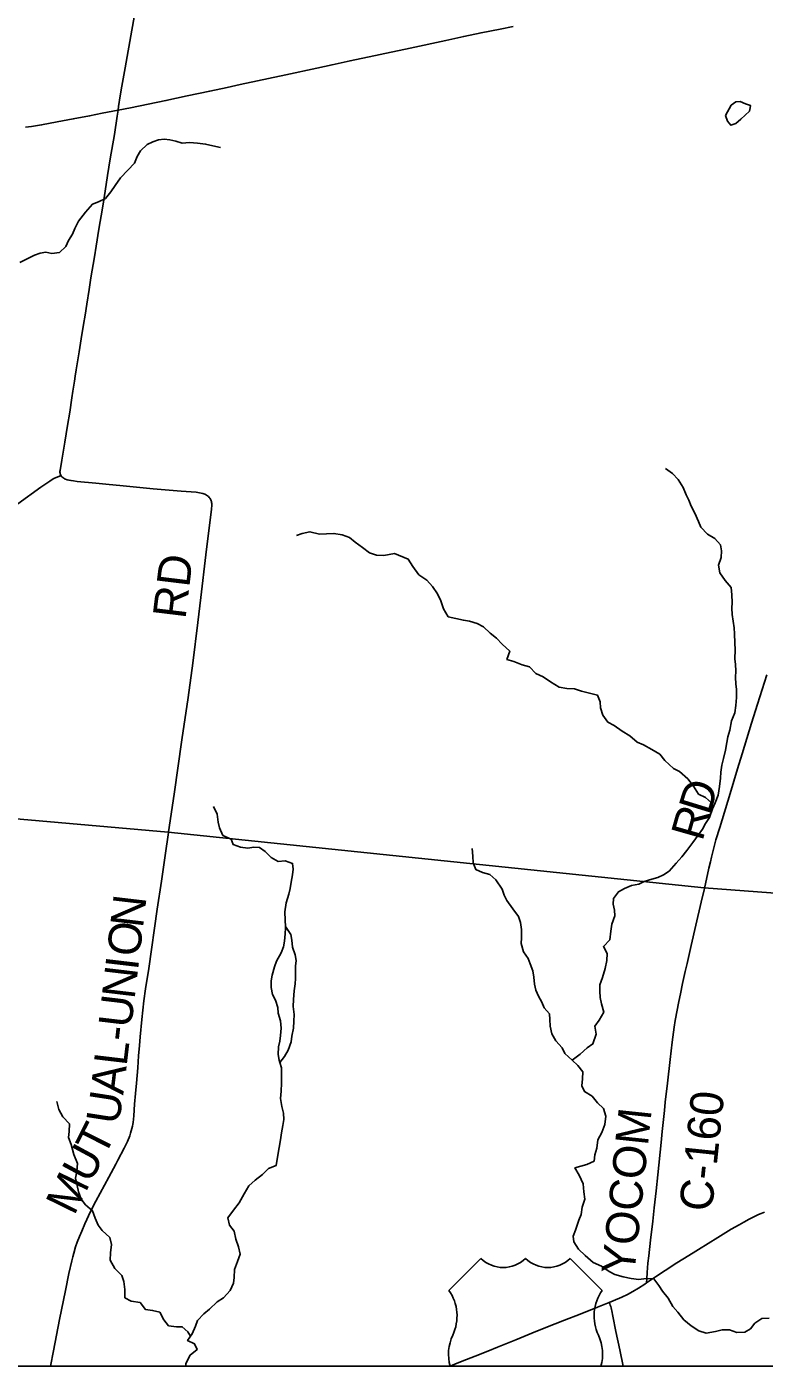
# Model space of a CAD drawing. Extents: x 0 to 1101, y 0 to 440.
# Drawn here: x 847.022 to 848.291, y 368.306 to 370.612 of the extents above; entities that cross this region are included whole.
import ezdxf

# ---------------------------------------------------------------- set-up
doc = ezdxf.new("R2010")
doc.units = 0
for name, color, linetype in [('GM_X_County_Road', 7, 'Continuous'), ('GM_X_County_Road_Text', 7, 'Continuous'), ('GM_X_Major_River_Text', 7, 'Continuous'), ('GM_X_Minor_Lake', 7, 'Continuous'), ('GM_X_Minor_River', 7, 'Continuous'), ('GM_X_Township', 7, 'Continuous'), ('GM_X_Township_Road', 7, 'Continuous'), ('GM_X_US_Location', 7, 'Continuous'), ('GM_X_US_Route', 7, 'Continuous'), ('SH_Cut_Line', 7, 'Continuous')]:
    doc.layers.add(name, color=color, linetype=linetype)

msp = doc.modelspace()

# ---------------------------------------------------------------- linework, layer by layer
at = {"layer": 'GM_X_County_Road'}
for points in [[(847.1792, 370.4686), (847.18, 370.4749), (847.183, 370.4935), (847.1858, 370.51), (847.1913, 370.5418), (847.2028, 370.6067), (847.2095, 370.6452)], [(847.1792, 370.4686), (847.2008, 370.473), (847.2616, 370.4855), (847.298, 370.4935), (847.3369, 370.5018), (847.3667, 370.5081), (847.3892, 370.5129), (847.4681, 370.5299), (847.521, 370.5412), (847.5476, 370.5472), (847.5786, 370.554), (847.6819, 370.5759), (847.7432, 370.5891), (847.7742, 370.5959), (847.804, 370.6021), (847.8369, 370.6086), (847.8595, 370.6129)], [(847.0197, 370.4396), (847.0251, 370.44), (847.0299, 370.4407), (847.0476, 370.4436), (847.0745, 370.4486), (847.102, 370.4537), (847.1301, 370.4591), (847.152, 370.4635), (847.1792, 370.4686)], [(847.0807, 369.84), (847.08, 369.8414), (847.0796, 369.8426), (847.0793, 369.844), (847.0791, 369.8454), (847.0791, 369.8467), (847.0793, 369.8484), (847.0821, 369.8662), (847.0844, 369.8801), (847.0874, 369.8974), (847.0923, 369.9261), (847.0961, 369.9488), (847.0997, 369.9734), (847.1014, 369.9851), (847.1039, 370.0023), (847.1052, 370.0108), (847.107, 370.0219), (847.1121, 370.0525), (847.1158, 370.0752), (847.1197, 370.0997), (847.1223, 370.1157), (847.1253, 370.1347), (847.1293, 370.1598), (847.1325, 370.1801), (847.1383, 370.2163), (847.1413, 370.2346), (847.1461, 370.2641), (847.1522, 370.3002), (847.155, 370.318), (847.1609, 370.3561), (847.1657, 370.3849), (847.1728, 370.4272), (847.1778, 370.4587), (847.1792, 370.4686)], [(847.266, 369.226), (847.2754, 369.2908), (847.2889, 369.3843), (847.2996, 369.4575), (847.3079, 369.5165), (847.3166, 369.5868), (847.3218, 369.6294), (847.3302, 369.7029), (847.3353, 369.7448), (847.3397, 369.7812), (847.3403, 369.7894), (847.3403, 369.7913), (847.3401, 369.7932), (847.3398, 369.7948), (847.3393, 369.7964), (847.3388, 369.7976), (847.3382, 369.7988), (847.3371, 369.8005), (847.3359, 369.802), (847.3347, 369.8033), (847.3331, 369.8048), (847.3315, 369.8059), (847.3299, 369.8069), (847.3285, 369.8076), (847.327, 369.8083), (847.3248, 369.809), (847.3221, 369.8096), (847.3134, 369.8108), (847.2879, 369.8128), (847.2396, 369.817), (847.1877, 369.822), (847.158, 369.8248), (847.1407, 369.8264), (847.1086, 369.8296), (847.1026, 369.8304), (847.0981, 369.831), (847.0947, 369.8317), (847.0915, 369.8325), (847.0888, 369.8334), (847.087, 369.8342), (847.0855, 369.8351), (847.084, 369.8361), (847.083, 369.837), (847.082, 369.8381), (847.081, 369.8393), (847.0807, 369.84)], [(848.1884, 369.1288), (848.1963, 369.1634), (848.1987, 369.1743), (848.2007, 369.1827), (848.2039, 369.196), (848.2083, 369.2121), (848.2147, 369.2336), (848.2326, 369.2924), (848.2455, 369.3346), (848.2535, 369.3607), (848.2694, 369.413), (848.2799, 369.4462), (848.2959, 369.4965)], [(847.0629, 368.3059), (847.068, 368.3322), (847.0785, 368.3865), (847.0884, 368.4365), (847.0945, 368.4657), (847.0993, 368.4875), (847.101, 368.4943), (847.1027, 368.5007), (847.106, 368.5113), (847.1087, 368.5193), (847.1127, 368.5293), (847.1165, 368.5385), (847.1219, 368.551), (847.1319, 368.5724), (847.1409, 368.5901), (847.1631, 368.6317), (847.1752, 368.6541), (847.1787, 368.6607), (847.1895, 368.6811), (847.1951, 368.6929), (847.1991, 368.7027), (847.2005, 368.7071), (847.2018, 368.7111), (847.2029, 368.7151), (847.2037, 368.719), (847.2044, 368.7225), (847.2049, 368.7258), (847.2056, 368.7312), (847.206, 368.7369), (847.2076, 368.7574), (847.209, 368.7753), (847.2106, 368.7933), (847.2129, 368.8199), (847.2145, 368.8403), (847.2159, 368.8583), (847.2171, 368.8731), (847.2199, 368.9028), (847.2236, 368.9349), (847.2266, 368.9557), (847.2319, 368.9908), (847.2465, 369.0929), (847.2538, 369.1414), (847.2573, 369.1654), (847.2601, 369.1851), (847.2659, 369.225), (847.266, 369.226)], [(848.0889, 368.4495), (848.0893, 368.4563), (848.09, 368.4673), (848.0913, 368.4832), (848.0928, 368.4961), (848.0958, 368.5232), (848.0996, 368.5559), (848.1022, 368.5787), (848.1053, 368.6078), (848.108, 368.6356), (848.1139, 368.6912), (848.1158, 368.7103), (848.1196, 368.7461), (848.1211, 368.7604), (848.1247, 368.7931), (848.1295, 368.8338), (848.1331, 368.864), (848.1363, 368.8899), (848.1381, 368.9015), (848.1443, 368.9338), (848.1471, 368.9472), (848.1509, 368.9648), (848.1555, 368.9854), (848.1587, 368.9993), (848.1657, 369.0302), (848.1738, 369.0653), (848.183, 369.1052), (848.1878, 369.1264), (848.1884, 369.1288)]]:
    msp.add_lwpolyline(points, dxfattribs=at)
msp.add_lwpolyline([(844.6555, 368.3059), (849.3843, 368.3059), (849.458, 369.0211), (849.1756, 369.0468), (848.9835, 369.0702), (848.1881, 369.1294), (847.2656, 369.2256), (846.5466, 369.2884), (846.0672, 369.3302), (844.8955, 369.3794), (844.7671, 369.3901), (844.6729, 368.4734)], close=True, dxfattribs=at)
at = {"layer": 'GM_X_Major_River_Text'}
for p, q in [((847.8036, 368.4914), (847.7487, 368.4365)), ((848.0124, 368.4365), (847.9575, 368.4914)), ((847.7507, 368.3059), (848.0104, 368.3059))]:
    msp.add_line(p, q, dxfattribs=at)
for centre, radius, start, end in [((847.8421, 368.5307), 0.0549, 225.573, 314.427), ((847.919, 368.5307), 0.0549, 225.573, 314.427), ((847.6857, 368.3924), 0.0769, 334.5471, 35.0009), ((848.0754, 368.3924), 0.0769, 144.9991, 205.4529), ((847.8248, 368.3266), 0.0769, 154.8319, 195.6613), ((847.9363, 368.3266), 0.0769, 344.3387, 25.1681)]:
    msp.add_arc(centre, radius, start, end, dxfattribs=at)
at = {"layer": 'GM_X_Minor_Lake'}
for points in [[(848.2672, 370.4728), (848.2679, 370.4768), (848.2589, 370.4796), (848.2499, 370.4839), (848.2423, 370.4833), (848.2347, 370.4773), (848.2249, 370.4596)], [(848.2249, 370.4596), (848.2282, 370.4501), (848.2337, 370.4428), (848.2425, 370.4457), (848.2513, 370.4531), (848.2586, 370.4602), (848.2663, 370.4673), (848.2672, 370.4728)]]:
    msp.add_lwpolyline(points, dxfattribs=at)
at = {"layer": 'GM_X_Minor_River'}
for points in [[(847.0099, 370.2067), (847.0229, 370.213), (847.0355, 370.2189), (847.0451, 370.2226), (847.0546, 370.2243), (847.0652, 370.2223), (847.0781, 370.2236), (847.0893, 370.2341), (847.0936, 370.2447), (847.1006, 370.2552), (847.1045, 370.2651), (847.1108, 370.2779), (847.1232, 370.2933), (847.1351, 370.3068), (847.1454, 370.3108), (847.1573, 370.3168), (847.1666, 370.3284), (847.1739, 370.3389), (847.1832, 370.3525), (847.1959, 370.3656), (847.2075, 370.3776), (847.2122, 370.3893), (847.2177, 370.3991), (847.2292, 370.41), (847.2392, 370.4144), (847.2487, 370.4177), (847.2586, 370.4187)], [(847.2586, 370.4187), (847.2681, 370.4178), (847.2783, 370.4154), (847.2892, 370.4122), (847.3022, 370.4132), (847.3158, 370.4122), (847.3298, 370.4105), (847.3423, 370.4077), (847.3556, 370.4048)], [(847.9609, 368.8331), (847.9746, 368.8432), (847.9868, 368.854), (847.9964, 368.861), (848.0023, 368.8776), (847.9999, 368.8913), (848.0073, 368.9018), (848.0151, 368.9157), (848.0111, 368.9298), (848.009, 368.9409), (848.0085, 368.9515), (848.0086, 368.9629), (848.013, 368.9753), (848.0178, 368.9908), (848.0207, 369.0048), (848.0208, 369.0166), (848.0146, 369.0284), (848.0254, 369.0404), (848.0275, 369.0548), (848.0292, 369.0673), (848.0344, 369.0816), (848.0338, 369.0911), (848.0313, 369.1014), (848.0322, 369.1112), (848.0403, 369.1229), (848.051, 369.1284), (848.0632, 369.1335), (848.0754, 369.136), (848.0849, 369.1407), (848.0978, 369.1447), (848.1084, 369.1476), (848.118, 369.152), (848.1279, 369.1586), (848.1399, 369.1721), (848.1495, 369.1833), (848.1584, 369.1942), (848.1684, 369.2077), (848.1777, 369.2201), (848.1851, 369.2306), (848.1905, 369.2403), (848.1971, 369.2509), (848.2023, 369.2656), (848.207, 369.2761), (848.2121, 369.2893), (848.2146, 369.3041), (848.2164, 369.3188), (848.2169, 369.3287), (848.2186, 369.3412), (848.2214, 369.3525), (848.2247, 369.3669), (848.2272, 369.3798), (848.2285, 369.3896), (848.2321, 369.4013), (848.2353, 369.4172), (848.2405, 369.4308), (848.2426, 369.4436), (848.2439, 369.4573), (848.2434, 369.4713), (848.2424, 369.4808), (848.2422, 369.4918), (848.2424, 369.5032), (848.2418, 369.5142), (848.2409, 369.5241), (848.2411, 369.5393), (848.2409, 369.5518), (848.2404, 369.567), (848.2398, 369.5772), (848.2377, 369.589), (848.2364, 369.6004), (848.2358, 369.6111), (848.236, 369.6209), (848.2358, 369.6342), (848.2345, 369.6468), (848.2241, 369.6591), (848.2152, 369.6721), (848.2124, 369.6854), (848.2172, 369.6986), (848.2181, 369.71), (848.216, 369.7203), (848.2064, 369.7315), (848.194, 369.7385), (848.1821, 369.7508), (848.1785, 369.7604), (848.1719, 369.7749), (848.1657, 369.7871), (848.1617, 369.7971), (848.1573, 369.8066), (848.1518, 369.8188), (848.1433, 369.8326), (848.1337, 369.8434), (848.1213, 369.852)], [(847.6548, 369.7056), (847.6368, 369.7021), (847.6239, 369.7026), (847.6121, 369.7066), (847.5997, 369.7155), (847.5873, 369.7252), (847.5776, 369.7329), (847.5647, 369.7376), (847.5507, 369.7401), (847.5378, 369.7391), (847.5257, 369.7389), (847.5094, 369.7429), (847.4961, 369.7397), (847.4865, 369.7364)], [(848.203, 369.2671), (848.2009, 369.2762), (848.1901, 369.2855), (848.1785, 369.291), (848.1696, 369.3048), (848.1596, 369.3171), (848.1454, 369.3299), (848.1353, 369.335), (848.1204, 369.3492), (848.1119, 369.3596), (848.098, 369.3678), (848.0838, 369.376), (848.0725, 369.3808), (848.0598, 369.3916), (848.0467, 369.3994), (848.0329, 369.4091), (848.0224, 369.415), (848.0135, 369.4272), (848.0095, 369.4398), (848.0089, 369.4497), (848.0046, 369.4612), (847.9929, 369.4644), (847.9771, 369.4681), (847.9647, 369.4724), (847.9514, 369.473), (847.9382, 369.4751), (847.9232, 369.4845), (847.9109, 369.493), (847.8981, 369.4985), (847.8873, 369.5101), (847.8749, 369.5137), (847.8603, 369.5193), (847.8486, 369.5229), (847.8534, 369.5372), (847.8403, 369.5492), (847.8306, 369.5596), (847.8198, 369.5685), (847.8079, 369.5793), (847.7974, 369.5848), (847.7838, 369.5888), (847.7736, 369.5905), (847.7608, 369.5934), (847.7476, 369.5966), (847.7395, 369.61), (847.7348, 369.6238), (847.729, 369.636), (847.7201, 369.6487), (847.7108, 369.6594), (847.697, 369.6688), (847.6866, 369.6833), (847.6785, 369.6956), (847.6548, 369.7056)], [(847.4673, 369.0631), (847.4668, 369.0742), (847.4663, 369.0886), (847.4684, 369.1041), (847.4731, 369.1185), (847.4756, 369.1284), (847.4772, 369.1397), (847.4793, 369.1522), (847.4806, 369.1621), (847.4796, 369.1716), (847.4668, 369.1763), (847.4546, 369.175), (847.4425, 369.182), (847.4324, 369.1924), (847.4223, 369.199), (847.4128, 369.1995), (847.4025, 369.1981), (847.39, 369.1998), (847.3772, 369.2042), (847.3739, 369.2137), (847.3596, 369.22), (847.3537, 369.233), (847.3512, 369.2429), (847.3495, 369.2566), (847.3432, 369.2696)], [(847.9985, 368.6591), (847.9998, 368.6701), (848.003, 368.6814), (848.0051, 368.6958), (848.0121, 368.7082), (848.0169, 368.7222), (848.019, 368.7366), (848.0147, 368.7496), (848.0042, 368.7596), (847.9953, 368.7707), (847.9818, 368.7789), (847.9775, 368.7885), (847.9784, 368.8006), (847.979, 368.8131), (847.9708, 368.8235), (847.9608, 368.8331), (847.9481, 368.8444), (847.9437, 368.8539), (847.9329, 368.8662), (847.9259, 368.8781), (847.9228, 368.8914), (847.9226, 368.9028), (847.9216, 368.9127), (847.9127, 368.9231), (847.9083, 368.933), (847.9028, 368.9434), (847.8984, 368.9533), (847.8959, 368.9636), (847.8946, 368.9761), (847.8933, 368.9868), (847.8882, 368.9986), (847.8849, 369.0082), (847.8772, 369.0197), (847.8729, 369.0338), (847.8734, 369.0436), (847.8736, 369.0577), (847.8719, 369.0702), (847.8683, 369.0805), (847.8587, 369.0936), (847.8483, 369.1078), (847.8439, 369.1173), (847.8403, 369.1276), (847.8296, 369.1434), (847.8192, 369.1526), (847.8067, 369.1559), (847.7951, 369.161), (847.7904, 369.1725), (847.7898, 369.1842), (847.7885, 369.1975)], [(847.4673, 369.0631), (847.4674, 369.0605), (847.4669, 369.0502), (847.4655, 369.0377), (847.4639, 369.0279), (847.4596, 369.018), (847.4518, 369.0033), (847.4486, 368.9935), (847.4446, 368.9795), (847.4429, 368.9696), (847.4424, 368.9579), (847.4452, 368.9461), (847.45, 368.9365), (847.4544, 368.9235), (847.4547, 368.9136), (847.4587, 368.9007), (847.4596, 368.8881), (847.4587, 368.8756), (847.4574, 368.8654), (847.4554, 368.8559), (847.4548, 368.8426), (847.4565, 368.8331), (847.4578, 368.8288)], [(847.4578, 368.8288), (847.4654, 368.839), (847.472, 368.85), (847.4771, 368.8643), (847.4784, 368.8742), (847.4813, 368.8882), (847.4814, 368.9), (847.482, 368.9117), (847.4806, 368.9254), (847.4812, 368.9376), (847.4825, 368.9524), (847.4842, 368.9641), (847.4847, 368.9736), (847.4845, 368.9846), (847.4847, 368.9949), (847.4856, 369.0044), (847.4842, 369.0143), (847.4791, 369.0276), (847.4785, 369.0398), (847.4763, 369.0493), (847.4673, 369.0631)], [(847.4538, 368.6657), (847.4567, 368.6826), (847.4588, 368.6959), (847.4605, 368.7077), (847.4625, 368.7202), (847.4642, 368.7308), (847.4636, 368.7418), (847.4611, 368.7529), (847.459, 368.7669), (847.4596, 368.7798), (847.4605, 368.7931), (847.4604, 368.8072), (847.4605, 368.8197), (847.4578, 368.8288)], [(847.103, 368.6702), (847.0983, 368.6879), (847.0936, 368.6997), (847.0949, 368.71), (847.0958, 368.7232), (847.0842, 368.7356), (847.0772, 368.7482), (847.0736, 368.7615)], [(847.3038, 368.3576), (847.2994, 368.3649), (847.2896, 368.3737), (847.2798, 368.3737), (847.2662, 368.3754), (847.2579, 368.3857), (847.2508, 368.399), (847.2384, 368.4021), (847.2263, 368.4037), (847.2169, 368.4156), (847.2014, 368.418), (847.1905, 368.4237), (847.191, 368.4381), (847.1889, 368.4518), (847.1855, 368.4621), (847.1735, 368.4739), (847.1653, 368.4884), (847.1662, 368.5009), (847.1678, 368.5157), (847.1649, 368.5274), (847.1517, 368.5393), (847.145, 368.5488), (847.1398, 368.561), (847.135, 368.5736), (847.1233, 368.5835), (847.1155, 368.5934), (847.1111, 368.6064), (847.1085, 368.617), (847.1056, 368.6295), (847.1079, 368.642), (847.1092, 368.6549), (847.103, 368.6702)], [(847.4154, 368.6263), (847.4276, 368.6361), (847.4383, 368.6466), (847.4512, 368.6515), (847.4538, 368.6657)], [(848.3, 368.3887), (848.2871, 368.3881), (848.2753, 368.3802), (848.2676, 368.3705), (848.2581, 368.3645), (848.2444, 368.3639), (848.2316, 368.3685), (848.2191, 368.3686), (848.2073, 368.3654), (848.1914, 368.3628), (848.1786, 368.3668), (848.1654, 368.3756), (848.153, 368.3856), (848.1425, 368.399), (848.1343, 368.4089), (848.1261, 368.423), (848.116, 368.4352), (848.1097, 368.4448), (848.1014, 368.4566), (848.0882, 368.4571), (848.0753, 368.4553), (848.0621, 368.457), (848.0488, 368.4597), (848.0345, 368.4637), (848.0243, 368.4691), (848.0112, 368.4783), (847.9972, 368.4845), (847.9833, 368.4968), (847.9717, 368.5075), (847.9635, 368.5201), (847.9624, 368.5299), (847.9663, 368.5401), (847.9722, 368.5571), (847.9764, 368.567), (847.9781, 368.5795), (847.9828, 368.5934), (847.9806, 368.6063), (847.9796, 368.62), (847.9726, 368.6349), (847.9655, 368.6474), (847.9859, 368.653), (847.9985, 368.6591)], [(847.2958, 368.3059), (847.2955, 368.3107), (847.3032, 368.325), (847.315, 368.3344), (847.3109, 368.3447), (847.2989, 368.3501), (847.3065, 368.3618), (847.3123, 368.375), (847.3158, 368.3848), (847.3265, 368.3961), (847.3364, 368.404), (847.3497, 368.4168), (847.3604, 368.4239), (847.3718, 368.436), (847.378, 368.4488), (847.3788, 368.4586), (847.3793, 368.4723), (847.3847, 368.4863), (847.3894, 368.4991), (847.3865, 368.5113), (847.3817, 368.5246), (847.3791, 368.5383), (847.3709, 368.549), (847.3683, 368.5615), (847.3779, 368.5747), (847.3878, 368.5875), (847.3963, 368.6026), (847.404, 368.6166), (847.4154, 368.6263)]]:
    msp.add_lwpolyline(points, dxfattribs=at)
at = {"layer": 'GM_X_Township'}
msp.add_lwpolyline([(849.9545, 374.031), (849.8439, 372.9428), (849.801, 372.4523), (849.7903, 372.3822), (849.6279, 370.8315), (849.4693, 369.1354), (849.458, 369.0211), (849.1756, 369.0468), (848.9835, 369.0702), (848.1881, 369.1294), (847.2656, 369.2256), (846.5466, 369.2884), (846.0672, 369.3302), (844.8955, 369.3794), (844.7671, 369.3901), (844.7764, 369.459), (844.8107, 369.7452), (844.9343, 370.7914), (845.2, 372.8166), (845.355, 374.0482)], dxfattribs=at)
at = {"layer": 'GM_X_Township_Road'}
for points in [[(847.0063, 369.7912), (847.0462, 369.8196), (847.0616, 369.8302), (847.0656, 369.8327), (847.0685, 369.8343), (847.0724, 369.8362), (847.077, 369.8383), (847.0807, 369.84)], [(848.0483, 368.3059), (848.0483, 368.3061), (848.0427, 368.3342), (848.0361, 368.3655), (848.0309, 368.3923), (848.0291, 368.401), (848.0286, 368.4038), (848.0279, 368.4065), (848.0272, 368.4088), (848.0264, 368.4109), (848.0255, 368.4135), (848.0247, 368.4157)]]:
    msp.add_lwpolyline(points, dxfattribs=at)
at = {"layer": 'GM_X_US_Route'}
msp.add_lwpolyline([(847.7509, 368.3059), (847.759, 368.3092), (847.7717, 368.3143), (847.7936, 368.3231), (847.8154, 368.3319), (847.8322, 368.3387), (847.8639, 368.3515), (847.8912, 368.3626), (847.9156, 368.3723), (847.9475, 368.3849), (847.9747, 368.3956), (848.0043, 368.4074), (848.0247, 368.4157), (848.0311, 368.4183), (848.046, 368.4248), (848.0558, 368.4296), (848.0651, 368.4346), (848.0747, 368.4401), (848.0856, 368.4473), (848.0889, 368.4495), (848.1043, 368.4598), (848.1206, 368.4706), (848.1412, 368.484), (848.1616, 368.4968), (848.1735, 368.5041), (848.1992, 368.5198), (848.2072, 368.5246), (848.2347, 368.5416), (848.248, 368.5496), (848.2562, 368.5541), (848.2655, 368.559), (848.2711, 368.5619), (848.2767, 368.5646), (848.2816, 368.567), (848.2864, 368.5689), (848.292, 368.5712)], dxfattribs=at)
at = {"layer": 'SH_Cut_Line'}
msp.add_lwpolyline([(837.3258, 368.3059), (850.9258, 368.3059), (850.9258, 375.8797), (850.1463, 375.9688), (849.9034, 375.9956), (849.0627, 376.0925), (847.7946, 376.221), (847.4662, 376.2566), (846.6778, 376.3437), (845.8289, 376.4273), (845.6523, 376.4464), (845.5612, 376.461), (845.4182, 376.4736), (844.4941, 376.5699), (843.7743, 376.6401)], dxfattribs=at)

# ---------------------------------------------------------------- texts
at = {"layer": 'GM_X_County_Road_Text'}
for s, height, rotation, p in [('RD', 0.05682, 83.0591, (847.295, 369.5914)), ('D', 0.0568, 72.8541, (848.1974, 369.2531)), ('R', 0.0568, 74.1071, (848.1848, 369.2085)), ('N', 0.0568, 83.2652, (847.2219, 369.0593)), ('O', 0.0568, 83.2599, (847.216, 369.0096)), ('I', 0.0568, 83.2632, (847.2133, 368.9864)), ('N', 0.0568, 83.2652, (847.2074, 368.9368)), ('U', 0.0568, 83.2599, (847.2016, 368.8871)), ('-', 0.0568, 83.2644, (847.1988, 368.864)), ('L', 0.0568, 83.2604, (847.1938, 368.8217)), ('A', 0.0568, 83.2859, (847.188, 368.7721)), ('U', 0.0568, 81.2274, (847.1801, 368.7205)), ('C-160', 0.05682, 84.0207, (848.2013, 368.5707)), ('T', 0.0568, 63.1683, (847.1549, 368.664)), ('YOCOM', 0.05682, 83.9426, (848.0675, 368.4618)), ('U', 0.0568, 61.641, (847.1304, 368.6185)), ('M', 0.0568, 63.8048, (847.1035, 368.5637))]:
    msp.add_text(s, height=height, rotation=rotation, dxfattribs=at).set_placement(p)
at = {"layer": 'GM_X_US_Location'}
for s in ['0', '/']:
    msp.add_text(s, height=0.000189, dxfattribs=at).set_placement((847.8805, 368.3641))
msp.add_text('36', height=0.000189, rotation=0, dxfattribs=at).set_placement((847.8414, 368.3249))

doc.saveas('drawing.dxf')
